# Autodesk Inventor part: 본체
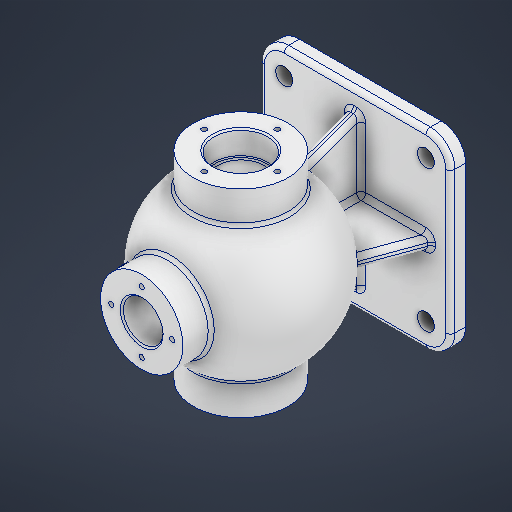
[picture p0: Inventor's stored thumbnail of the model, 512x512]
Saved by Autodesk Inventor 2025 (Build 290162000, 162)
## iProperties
Created: 2025-08
Part Number: 본체
Material: 알루미늄 6061
Document SubType Name: Sheet Metal
Designer: infra15
Density: 2.7 g/cm^3
Sheet Metal Rule: 기본값_mm
Appearance: 알루미늄 - 평지
Mass: 1525.54 g
Surface Area: 1176.74 cm^2
Volume: 565.016 cm^3
Author: infra15
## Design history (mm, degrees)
sketch "스케치1"
  geometry: L1 (-46.5, -62.5)-(46.5, -62.5); L2 (62.5, -46.5)-(62.5, 46.5); L3 (46.5, 62.5)-(-46.5, 62.5); L4 (-62.5, 46.5)-(-62.5, -46.5); L5 (-62.5, -62.5)-(62.5, 62.5); L6 (62.5, -62.5)-(-62.5, 62.5); A1 r 16 centre (46.5, 46.5) between (62.5, 46.5) and (46.5, 62.5); A2 r 16 centre (46.5, -46.5) between (46.5, -62.5) and (62.5, -46.5); A3 r 16 centre (-46.5, -46.5) between (-62.5, -46.5) and (-46.5, -62.5); A4 r 16 centre (-46.5, 46.5) between (-46.5, 62.5) and (-62.5, 46.5); 1 further point
  constraints: 12 end point, 8 point on circle, 8 point on line, 8 tangent, 4 centre point, 3 equal radius, 2 midpoint, 2 parallel, 1 horizontal, 1 perpendicular
  dimensions: "d0" = 125 distance of L6.end L5.end; "d1" = 125 distance of L5.end L6.start; "d2" = 16 radius of A1
extrude "돌출1" new body sketch "스케치1" distance "d3" = 10; taper "d4" = 0 deg
sketch "스케치2"
  geometry: L1 (46.5, -46.5)-(-46.5, -46.5); L2 (-46.5, -46.5)-(-46.5, 46.5); L3 (-46.5, 46.5)-(46.5, 46.5); L4 (46.5, 46.5)-(46.5, -46.5); L5 (46.5, -46.5)-(-46.5, 46.5); L6 (-46.5, -46.5)-(46.5, 46.5); C1 r 5.5 at (-46.5, 46.5); C2 r 5.5 at (46.5, 46.5); C3 r 5.5 at (46.5, -46.5); C4 r 5.5 at (-46.5, -46.5); 1 further point
  constraints: 12 end point, 4 centre point, 4 coincident, 2 midpoint, 2 parallel, 1 horizontal, 1 perpendicular
  dimensions: "d5" = 11 diameter of C1; "d6" = 11 diameter of C2; "d7" = 11 diameter of C3; "d8" = 11 diameter of C4; "d9" = 93 distance of L2.end L3.end; "d10" = 93 distance of L1.end L2.end
extrude "돌출2" cut sketch "스케치2" extent not by distance; stored distance "d11" = 0; taper "d12" = 0 deg
node "작업 평면1"
sketch "스케치3"
  geometry: L1 (0, 54)-(0, -54); L2 (0, 59.486)-(0, -58.647); L3 (-46.5, -62.5)-(46.5, -62.5) reference; L4 (10, -42.849)-(10, 42.849); A1 r 54 centre (0, 0) between (0, -54) and (0, 54); A2 r 44 centre (0, 0) between (10, -42.849) and (10, 42.849); 2 further points
  constraints: 6 end point, 4 point on circle, 2 centre point, 1 coincident, 1 midpoint, 1 perpendicular, 1 vertical, 1 vertical alignment, 1 other
  dimensions: "d14" = 108 diameter of A1; "d16" = 10 radial gap between concentric circles of A1 A2
revolve "회전1" sketch "스케치3" stored, may be unused: angle "d15" = 360 deg
node "작업 평면2"
sketch "스케치5"
  geometry: C1 r 10 at (0, 85) reference; C2 r 31 at (0, 85); 1 further point
  constraints: 1 centre point, 1 coincident
  dimensions: "d18" = 62 diameter of C2
extrude "돌출3" join sketch "스케치5" distance "d19" = 11; taper "d20" = 0 deg
feature "면 삭제1"
sketch "스케치9"
  geometry: C1 r 10 at (0, 0) reference; C2 r 15 at (0, 0); 1 further point
  constraints: 1 centre point, 1 coincident
  dimensions: "d28" = 30 diameter of C2
extrude "돌출7" cut sketch "스케치9" extent not by distance; stored distance "d29" = 0; taper "d30" = 0 deg
sketch "스케치10"
  geometry: C1 r 15 at (0, 0) reference; C2 r 17.5 at (0, 0); 1 further point
  constraints: 1 centre point, 1 coincident
  dimensions: "d31" = 35 diameter of C2
extrude "돌출8" cut sketch "스케치10" distance "d32" = 16; taper "d33" = 0 deg
sketch "스케치11"
  geometry: C1 r 17.5 at (0, 0) reference; 1 further point
extrude "돌출9" cut sketch "스케치11" distance "d34" = 16; taper "d35" = 0 deg
node "작업 평면3"
sketch "스케치12"
  geometry: C1 r 27 at (0, 0); 1 further point
  constraints: 1 centre point, 1 coincident
  dimensions: "d37" = 54 diameter of C1
extrude "돌출10" join sketch "스케치12" stored distance "d38" = 16; taper "d39" = 0 deg
sketch "스케치13"
  geometry: C1 r 13 at (0, 0); 1 further point
  constraints: 1 centre point, 1 coincident
  dimensions: "d40" = 26 diameter of C1
extrude "돌출11" cut sketch "스케치13" distance "d41" = 40.75; taper "d42" = 0 deg
sketch "스케치14"
  geometry: C1 r 15 at (0, 0) reference; A1 r 24 centre (0, 0) between (0, -24) and (-24, 0); 3 further points
  constraints: 4 point on circle, 1 centre point, 1 coincident
  dimensions: "d43" = 48 diameter of A1
hole "구멍1" sketch "스케치14" at (-24, 0), (24, 0), (0, 24), (0, -24) diameter "d44" = 3.242; stored, may be unused: countersink angle "d48" = 90 deg, drill point angle "d50" = 118 deg; dims "d45" = 12, "d46" = 4, "d47" = 2, "d49" = 15
sketch "스케치15"
  geometry: C1 r 1.621 at (0, 24) reference; C2 r 1.621 at (-24, 0) reference; C3 r 1.621 at (0, -24) reference; C4 r 1.621 at (24, 0) reference; 1 further point
hole "구멍2" sketch "스케치15" at (0, 24), (-24, 0), (0, -24), (24, 0) diameter "d51" = 3.242; stored, may be unused: countersink angle "d55" = 90 deg, drill point angle "d57" = 118 deg; dims "d52" = 12, "d53" = 4, "d54" = 2, "d56" = 15
sketch "스케치16"
  geometry: C1 r 13 at (0, 0) reference; A1 r 20 centre (0, 0) between (0, 20) and (20, 0); 3 further points
  constraints: 4 point on circle, 1 centre point, 1 coincident
  dimensions: "d58" = 40 diameter of A1
hole "구멍3" sketch "스케치16" at (0, 20), (20, 0), (-20, 0), (0, -20) diameter "d59" = 3.242; stored, may be unused: countersink angle "d63" = 90 deg, drill point angle "d65" = 118 deg; dims "d60" = 9, "d61" = 4, "d62" = 2, "d64" = 11
sketch "스케치18"
  geometry: L1 (50.5, 10)-(-50.5, 10); L2 (-50.5, 10)-(-42.857, 31); L3 (-42.857, 31)-(42.857, 31); L4 (42.857, 31)-(50.5, 10); 4 further points
  constraints: 8 end point, 1 horizontal, 1 midpoint, 1 parallel
  dimensions: "d70" = 70 deg angle of L1 L2; "d71" = 70 deg angle of L1 L4; "d72" = 12 distance of point (-62.5, 10) L1.end; "d73" = 12 distance of point (62.5, 10) L1.start; "d74" = 10 distance of point (0, 0) point (0, 10); "d75" = 21 distance between parallel lines of L1 L3
extrude "돌출12" join sketch "스케치18" stored distance "d76" = 8; taper "d77" = 0 deg
feature "면 삭제2"
sketch "스케치19"
  geometry: L1 (-50.5, 10)-(50.5, 10); L2 (50.5, 10)-(42.857, 31); L3 (-50.5, 10)-(-42.857, 31); L4 (-42.857, 31)-(42.857, 31); 3 further points
  constraints: 8 end point, 2 horizontal
  dimensions: "d78" = 12 distance of point (62.5, 10) L1.end; "d79" = 12 distance of point (-62.5, 10) L1.start; "d80" = 10 distance from line of point (0, 0) L1; "d81" = 70 deg angle of L1 L3; "d82" = 70 deg angle of L1 L2; "d83" = 21 distance between parallel lines of L1 L4
extrude "돌출13" join sketch "스케치19" stored distance "d84" = 8; taper "d85" = 0 deg
feature "면 삭제3"
feature "면 삭제4"
fillet "모깎기1" dims "d86" = 3
fillet "모깎기2" dims "d87" = 3
node "작업 평면4"
sketch "스케치20" dims "CornerReliefSize" = 2 (derived)
  geometry: L1 (-20.562, 144.002)-(20.916, 144.002); L2 (20.916, 144.002)-(20.916, 137.998); L3 (20.916, 137.998)-(-20.562, 137.998); L4 (-20.562, 137.998)-(-20.562, 144.002); L5 (27, 150)-(-27, 150) reference; L6 (65, 116)-(65, 54) reference; 3 further points
  constraints: 2 midpoint, 1 horizontal, 2 other
  dimensions: "d89" = 9 distance from line of L5 point (20.916, 141); "d90" = 41.47897 distance of L1.start L1.end; "d91" = 6.00407 distance of L3.end L1.start; "d92" = 64.82299 distance from line of L6 point (0.177, 144.002)
feature "엠보싱1" sketch "스케치20" dims "d3" = 10, "d4" = 0, "d93" = 0.5, "d94" = 0
chamfer "모따기1" distance "d95" = 1; stored, may be unused: second distance "d96" = 2, angle "d97" = 45 deg
chamfer "모따기3" distance "d101" = 1; stored, may be unused: second distance "d102" = 2, angle "d103" = 45 deg
chamfer "모따기5" distance "d107" = 1; stored, may be unused: second distance "d108" = 2, angle "d109" = 45 deg
fillet "모깎기3" dims "d110" = 0.6
fillet "모깎기4" dims "d111" = 0.6
feature "η耀ι耀λ耀ν耀ο耀ρ耀σ耀υ耀" dims "d0" = 125, "d1" = 125, "d2" = 16, "d3" = 10, "d4" = 0, "d5" = 11, "d6" = 11, "d7" = 11, "d8" = 11, "d9" = 93, "d10" = 93, "d11" = 0, "d12" = 0, "d13" = 85, "d14" = 108, "d15" = 360 deg, "d16" = 10, "d17" = 54, "d18" = 62, "d19" = 11, "d20" = 0, "d28" = 30, "d29" = 0, "d30" = 0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
node "솔리드1"
mirror "미러1"
feature "A9D066F2-1C7D-4E18-AEED-F7BC21143FA4" dims "d44" = 3.242, "d45" = 12, "d46" = 4, "d47" = 2, "d48" = 90 deg, "d49" = 15, "d50" = 118 deg
